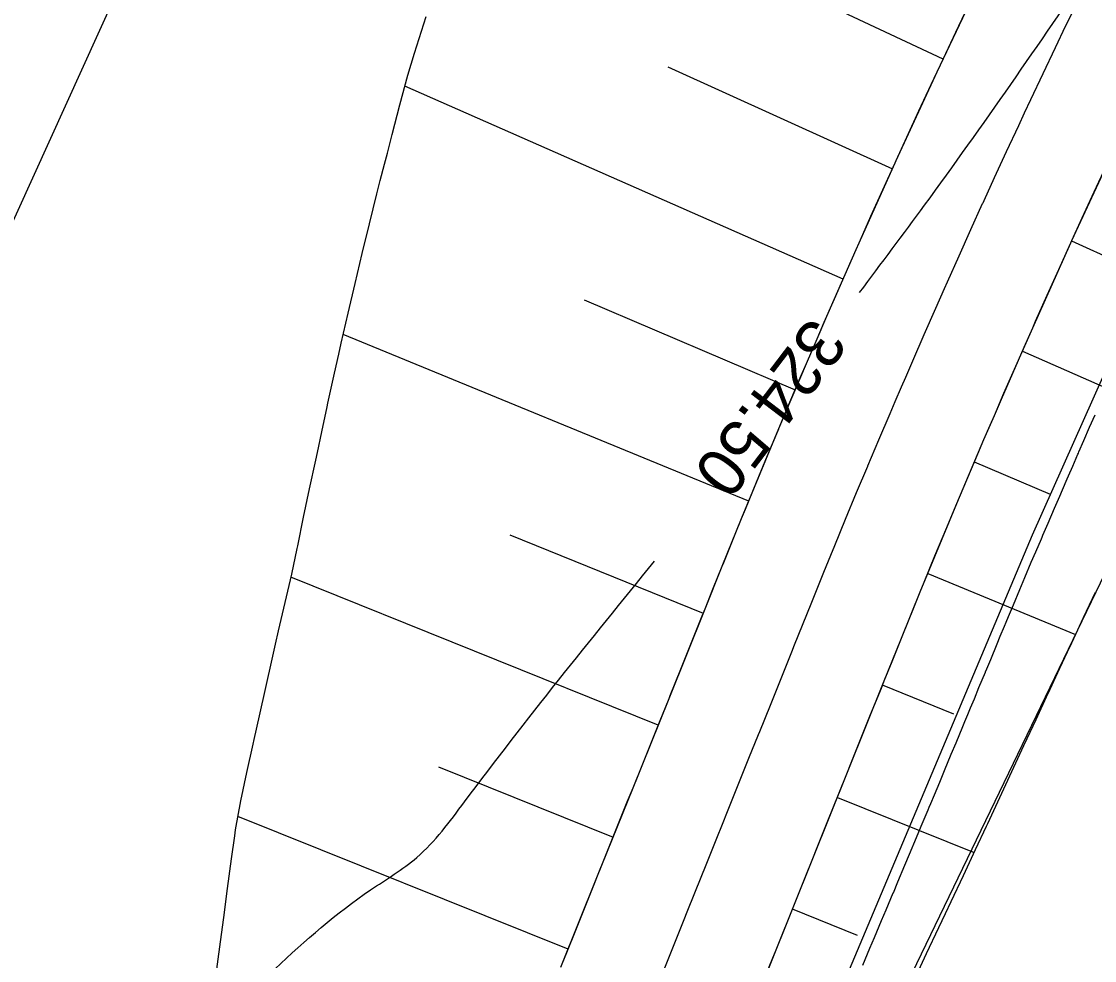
# Model space of a CAD drawing. Extents: x -564037 to -563827, y -1163561 to -1163412.
# Drawn here: x -563980.78 to -563969.67, y -1163490.36 to -1163480.64 of the extents above; entities that cross this region are included whole.
import ezdxf

# ---------------------------------------------------------------- set-up
doc = ezdxf.new("R2010")
doc.units = 0
for name, color, linetype in [('Default', 7, 'Continuous'), ('Definiční bod kú', 7, 'Continuous'), ('Line', 7, 'Continuous'), ('Vrstva 24', 7, 'Continuous'), ('Vrstva 25', 7, 'Continuous'), ('Vrstva 26', 7, 'Continuous')]:
    doc.layers.add(name, color=color, linetype=linetype)

msp = doc.modelspace()

# ---------------------------------------------------------------- linework, layer by layer
msp.add_lwpolyline([(-563976.663, -1163501.462), (-563964.742, -1163493.091), (-563961.829, -1163491.15), (-563957.41, -1163486.988), (-563956.735, -1163486.627), (-563953.281, -1163481.221), (-563953.993, -1163478.343), (-563957.796, -1163470.824), (-563957.81, -1163470.439), (-563957.835, -1163469.754), (-563958.239, -1163469.063), (-563958.187, -1163468.683), (-563959.529, -1163466.077), (-563960.166, -1163464.984), (-563964.31, -1163473.527), (-563966.903, -1163478.544), (-563968.406, -1163481.669), (-563970.316, -1163485.955), (-563973.278, -1163492.988), (-563976.735, -1163500.155), (-563977.161, -1163500.889), (-563977.363, -1163501.307)], close=True)
for points in [[(-563960.591, -1163493.664), (-563961.319, -1163493.948), (-563961.866, -1163494.161), (-563963.182, -1163494.674), (-563968.138, -1163497.33), (-563968.634, -1163497.596), (-563970.944, -1163498.688), (-563971.597, -1163498.997), (-563976.56, -1163501.343), (-563977.332, -1163501.295), (-563976.988, -1163500.693), (-563975.559, -1163498.192), (-563975.396, -1163497.906), (-563973.296, -1163494.084), (-563973.133, -1163493.747), (-563971.654, -1163490.682), (-563969.513, -1163486.248), (-563968.702, -1163484.611), (-563968.142, -1163483.478), (-563966.349, -1163479.855)], [(-563975.198, -1163490.428), (-563974.825, -1163489.5), (-563974.451, -1163488.572), (-563974.078, -1163487.645), (-563973.705, -1163486.717), (-563973.527, -1163486.276), (-563973.328, -1163485.785), (-563972.941, -1163484.852), (-563972.655, -1163484.178), (-563972.545, -1163483.923), (-563972.444, -1163483.689), (-563972.14, -1163482.998), (-563971.736, -1163482.1), (-563971.725, -1163482.077), (-563971.302, -1163481.16), (-563970.869, -1163480.247)], [(-563973.343, -1163491.175), (-563972.969, -1163490.247), (-563972.596, -1163489.319), (-563972.223, -1163488.391), (-563971.849, -1163487.464), (-563971.672, -1163487.023), (-563971.476, -1163486.542), (-563971.097, -1163485.627), (-563970.817, -1163484.966), (-563970.709, -1163484.716), (-563970.61, -1163484.487), (-563970.312, -1163483.809), (-563969.916, -1163482.93), (-563969.906, -1163482.907), (-563969.49, -1163482.008), (-563969.066, -1163481.113), (-563968.97, -1163480.914), (-563968.633, -1163480.223)], [(-563975.175, -1163490.37), (-563975.064, -1163490.095), (-563974.953, -1163489.819), (-563974.842, -1163489.544), (-563974.825, -1163489.5), (-563974.732, -1163489.269), (-563974.621, -1163488.994), (-563974.51, -1163488.718), (-563974.451, -1163488.572), (-563974.399, -1163488.443), (-563974.288, -1163488.168), (-563974.177, -1163487.892), (-563974.078, -1163487.645), (-563974.067, -1163487.617), (-563973.956, -1163487.342), (-563973.845, -1163487.066), (-563973.734, -1163486.791), (-563973.705, -1163486.717), (-563973.623, -1163486.516), (-563973.527, -1163486.276), (-563973.512, -1163486.24), (-563973.4, -1163485.962), (-563973.328, -1163485.785), (-563973.287, -1163485.685), (-563973.173, -1163485.407), (-563973.058, -1163485.13), (-563972.942, -1163484.854), (-563972.941, -1163484.852), (-563972.826, -1163484.578), (-563972.708, -1163484.302), (-563972.655, -1163484.178), (-563972.59, -1163484.027), (-563972.545, -1163483.923), (-563972.471, -1163483.751), (-563972.351, -1163483.477), (-563972.23, -1163483.202), (-563972.14, -1163482.998), (-563972.109, -1163482.928), (-563971.987, -1163482.654), (-563971.864, -1163482.381), (-563971.74, -1163482.108), (-563971.736, -1163482.1), (-563971.725, -1163482.077), (-563971.615, -1163481.836), (-563971.49, -1163481.563), (-563971.363, -1163481.292), (-563971.302, -1163481.16), (-563971.236, -1163481.02), (-563971.108, -1163480.749), (-563970.98, -1163480.478)], [(-563974.136, -1163490.468), (-563974.025, -1163490.193), (-563973.915, -1163489.918), (-563973.897, -1163489.873), (-563973.804, -1163489.642), (-563973.693, -1163489.367), (-563973.582, -1163489.092), (-563973.524, -1163488.946), (-563973.471, -1163488.816), (-563973.361, -1163488.541), (-563973.25, -1163488.266), (-563973.15, -1163488.018), (-563973.139, -1163487.99), (-563973.028, -1163487.715), (-563972.917, -1163487.44), (-563972.807, -1163487.164), (-563972.777, -1163487.09), (-563972.696, -1163486.889), (-563972.599, -1163486.649), (-563972.585, -1163486.614), (-563972.474, -1163486.339), (-563972.402, -1163486.163), (-563972.361, -1163486.064), (-563972.249, -1163485.789), (-563972.135, -1163485.515), (-563972.02, -1163485.241), (-563972.019, -1163485.239), (-563971.905, -1163484.968), (-563971.789, -1163484.695), (-563971.736, -1163484.572), (-563971.672, -1163484.422), (-563971.627, -1163484.32), (-563971.554, -1163484.15), (-563971.435, -1163483.878), (-563971.316, -1163483.606), (-563971.226, -1163483.404), (-563971.195, -1163483.335), (-563971.074, -1163483.064), (-563970.952, -1163482.793), (-563970.83, -1163482.523), (-563970.826, -1163482.515), (-563970.816, -1163482.492), (-563970.706, -1163482.253), (-563970.582, -1163481.983), (-563970.457, -1163481.714), (-563970.396, -1163481.584), (-563970.331, -1163481.446), (-563970.205, -1163481.177), (-563970.077, -1163480.909), (-563969.968, -1163480.68), (-563969.949, -1163480.641), (-563969.87, -1163480.479)], [(-563978.77, -1163490.523), (-563978.73, -1163490.219), (-563978.713, -1163490.091), (-563978.69, -1163489.915), (-563978.649, -1163489.612), (-563978.608, -1163489.308), (-563978.575, -1163489.069), (-563978.566, -1163489.005), (-563978.513, -1163488.707), (-563978.449, -1163488.413), (-563978.384, -1163488.119), (-563978.374, -1163488.072), (-563978.319, -1163487.825), (-563978.253, -1163487.532), (-563978.187, -1163487.238), (-563978.152, -1163487.083), (-563978.121, -1163486.945), (-563978.054, -1163486.652), (-563977.986, -1163486.359), (-563977.93, -1163486.095), (-563977.923, -1163486.065), (-563977.862, -1163485.77), (-563977.8, -1163485.475), (-563977.737, -1163485.18), (-563977.72, -1163485.101), (-563977.674, -1163484.885), (-563977.619, -1163484.629), (-563977.611, -1163484.589), (-563977.542, -1163484.279), (-563977.498, -1163484.081), (-563977.473, -1163483.969), (-563977.402, -1163483.659), (-563977.329, -1163483.35), (-563977.256, -1163483.041), (-563977.255, -1163483.039), (-563977.18, -1163482.732), (-563977.103, -1163482.424), (-563977.068, -1163482.285), (-563977.025, -1163482.116), (-563976.995, -1163482), (-563976.946, -1163481.808), (-563976.865, -1163481.5), (-563976.782, -1163481.193), (-563976.715, -1163480.966), (-563976.691, -1163480.89), (-563976.594, -1163480.588)], [(-563978.77, -1163490.523), (-563978.73, -1163490.219), (-563978.713, -1163490.091), (-563978.69, -1163489.915), (-563978.649, -1163489.612), (-563978.608, -1163489.308), (-563978.575, -1163489.069), (-563978.566, -1163489.005), (-563978.513, -1163488.707), (-563978.449, -1163488.413), (-563978.384, -1163488.119), (-563978.374, -1163488.072), (-563978.319, -1163487.825), (-563978.253, -1163487.532), (-563978.187, -1163487.238), (-563978.152, -1163487.083), (-563978.121, -1163486.945), (-563978.054, -1163486.652), (-563977.986, -1163486.359), (-563977.93, -1163486.095), (-563977.923, -1163486.065), (-563977.862, -1163485.77), (-563977.8, -1163485.475), (-563977.737, -1163485.18), (-563977.72, -1163485.101), (-563977.674, -1163484.885), (-563977.619, -1163484.629), (-563977.611, -1163484.589), (-563977.542, -1163484.279), (-563977.498, -1163484.081), (-563977.473, -1163483.969), (-563977.402, -1163483.659), (-563977.329, -1163483.35), (-563977.256, -1163483.041), (-563977.255, -1163483.039), (-563977.18, -1163482.732), (-563977.103, -1163482.424), (-563977.068, -1163482.285), (-563977.025, -1163482.116), (-563976.995, -1163482), (-563976.946, -1163481.808), (-563976.865, -1163481.5), (-563976.782, -1163481.193), (-563976.715, -1163480.966), (-563976.691, -1163480.89), (-563976.594, -1163480.588)], [(-563973.098, -1163490.566), (-563972.987, -1163490.291), (-563972.969, -1163490.247), (-563972.876, -1163490.016), (-563972.765, -1163489.74), (-563972.655, -1163489.465), (-563972.596, -1163489.319), (-563972.544, -1163489.19), (-563972.433, -1163488.914), (-563972.322, -1163488.639), (-563972.223, -1163488.391), (-563972.211, -1163488.364), (-563972.101, -1163488.088), (-563971.99, -1163487.813), (-563971.879, -1163487.538), (-563971.849, -1163487.464), (-563971.768, -1163487.262), (-563971.672, -1163487.023), (-563971.657, -1163486.987), (-563971.547, -1163486.715), (-563971.476, -1163486.542), (-563971.436, -1163486.443), (-563971.324, -1163486.171), (-563971.212, -1163485.9), (-563971.098, -1163485.629), (-563971.097, -1163485.627), (-563970.984, -1163485.358), (-563970.869, -1163485.088), (-563970.817, -1163484.966), (-563970.753, -1163484.818), (-563970.709, -1163484.716), (-563970.636, -1163484.548), (-563970.519, -1163484.279), (-563970.401, -1163484.01), (-563970.312, -1163483.809), (-563970.282, -1163483.741), (-563970.162, -1163483.473), (-563970.041, -1163483.205), (-563969.92, -1163482.937), (-563969.916, -1163482.93), (-563969.906, -1163482.907), (-563969.798, -1163482.67), (-563969.675, -1163482.403), (-563969.551, -1163482.137)], [(-563971.537, -1163490.555), (-563971.41, -1163490.286), (-563971.283, -1163490.017), (-563971.216, -1163489.874), (-563971.157, -1163489.748), (-563971.03, -1163489.479), (-563970.904, -1163489.21), (-563970.791, -1163488.968), (-563970.778, -1163488.94), (-563970.653, -1163488.671), (-563970.527, -1163488.402), (-563970.402, -1163488.132), (-563970.368, -1163488.06), (-563970.277, -1163487.863), (-563970.168, -1163487.628), (-563970.152, -1163487.594), (-563970.03, -1163487.332), (-563969.952, -1163487.164), (-563969.908, -1163487.069), (-563969.785, -1163486.808), (-563969.662, -1163486.546)], [(-563971.537, -1163490.555), (-563971.41, -1163490.286), (-563971.283, -1163490.017), (-563971.216, -1163489.874), (-563971.157, -1163489.748), (-563971.03, -1163489.479), (-563970.904, -1163489.21), (-563970.791, -1163488.968), (-563970.778, -1163488.94), (-563970.653, -1163488.671), (-563970.527, -1163488.402), (-563970.402, -1163488.132), (-563970.368, -1163488.06), (-563970.277, -1163487.863), (-563970.168, -1163487.628), (-563970.152, -1163487.594), (-563970.03, -1163487.332), (-563969.952, -1163487.164), (-563969.908, -1163487.069), (-563969.785, -1163486.808), (-563969.662, -1163486.546)]]:
    msp.add_lwpolyline(points)
at = {"layer": 'Default'}
msp.add_lwpolyline([(-563972.072, -1163490.408), (-563971.998, -1163490.232), (-563971.95, -1163490.12), (-563971.877, -1163489.946), (-563971.829, -1163489.833), (-563971.756, -1163489.659), (-563971.756, -1163489.659), (-563971.755, -1163489.658), (-563971.707, -1163489.544), (-563971.635, -1163489.372), (-563971.587, -1163489.257), (-563971.515, -1163489.086), (-563971.466, -1163488.969), (-563971.395, -1163488.799), (-563971.384, -1163488.773), (-563971.368, -1163488.735), (-563971.33, -1163488.644), (-563971.275, -1163488.512), (-563971.225, -1163488.393), (-563971.155, -1163488.224), (-563971.105, -1163488.105), (-563971.036, -1163487.937), (-563971.014, -1163487.885), (-563970.984, -1163487.812), (-563970.955, -1163487.744), (-563970.916, -1163487.65), (-563970.868, -1163487.533), (-563970.802, -1163487.373), (-563970.8, -1163487.368), (-563970.797, -1163487.363), (-563970.747, -1163487.242), (-563970.68, -1163487.081), (-563970.647, -1163487.002), (-563970.604, -1163486.898), (-563970.586, -1163486.855), (-563970.563, -1163486.799), (-563970.511, -1163486.677), (-563970.445, -1163486.518), (-563970.392, -1163486.395), (-563970.326, -1163486.237), (-563970.28, -1163486.13), (-563970.222, -1163485.995), (-563970.215, -1163485.978), (-563970.206, -1163485.957), (-563970.153, -1163485.832), (-563970.086, -1163485.676), (-563970.032, -1163485.551), (-563969.965, -1163485.396), (-563969.955, -1163485.372), (-563969.942, -1163485.342), (-563969.897, -1163485.24), (-563969.844, -1163485.116), (-563969.839, -1163485.106), (-563969.834, -1163485.094), (-563969.783, -1163484.977), (-563969.722, -1163484.837), (-563969.666, -1163484.709)], dxfattribs=at)
at = {"layer": 'Definiční bod kú'}
msp.add_lwpolyline([(-564036.505, -1163529.976), (-564035.88, -1163528.59), (-564032.62, -1163523.46), (-564027.5, -1163518.53), (-564023.88, -1163515.79), (-564019.18, -1163512.89), (-564014.48, -1163510.5), (-564004.65, -1163507.04), (-563996.46, -1163502.51), (-563993.72, -1163500.97), (-563990.58, -1163498.69), (-563987.18, -1163495.32), (-563983.19, -1163487.81), (-563979.82, -1163480.39), (-563975.55, -1163472.37), (-563971.76, -1163466.68), (-563970.57, -1163458.32), (-563969.42, -1163449.87), (-563967.93, -1163441.99), (-563966.12, -1163434.66), (-563963.95, -1163427.04), (-563963.19, -1163422.98), (-563961.48, -1163418.93), (-563957.126, -1163412.494)], dxfattribs=at)
at = {"layer": 'Line'}
for p, q in [((-563971.24, -1163481.029), (-563975.992, -1163478.796)), ((-563974.092, -1163481.106), (-563971.765, -1163482.164)), ((-563972.275, -1163483.305), (-563976.813, -1163481.308)), ((-563969.08, -1163483.289), (-563969.908, -1163482.911)), ((-563974.958, -1163483.521), (-563972.771, -1163484.452)), ((-563973.253, -1163485.605), (-563977.452, -1163483.877)), ((-563970.418, -1163484.052), (-563968.806, -1163484.762)), ((-563970.128, -1163485.534), (-563970.916, -1163485.199)), ((-563975.726, -1163485.954), (-563973.723, -1163486.764)), ((-563974.19, -1163487.923), (-563977.994, -1163486.392)), ((-563971.398, -1163486.352), (-563969.867, -1163486.983)), ((-563971.129, -1163487.809), (-563971.868, -1163487.51)), ((-563976.466, -1163488.355), (-563974.657, -1163489.083)), ((-563972.335, -1163488.67), (-563970.918, -1163489.24)), ((-563975.123, -1163490.242), (-563978.542, -1163488.867)), ((-563972.126, -1163490.101), (-563972.801, -1163489.829))]:
    msp.add_line(p, q, dxfattribs=at)
at = {"layer": 'Vrstva 24'}
for points in [[(-563987.107, -1163486.915), (-563987.454, -1163489.613), (-563987.517, -1163490.15), (-563987.54, -1163490.422), (-563987.53, -1163490.559), (-563987.493, -1163490.695), (-563987.417, -1163490.784), (-563987.298, -1163490.832), (-563987.065, -1163490.801), (-563986.897, -1163490.636), (-563986.866, -1163490.616), (-563986.653, -1163490.561), (-563986.65, -1163490.24), (-563986.645, -1163490.2), (-563986.382, -1163489.381), (-563986.092, -1163488.576), (-563985.799, -1163487.775), (-563985.528, -1163486.967), (-563985.38, -1163486.476), (-563984.961, -1163484.997), (-563984.678, -1163484.011), (-563984.372, -1163483.032), (-563984.225, -1163482.649), (-563983.962, -1163482.075), (-563983.672, -1163481.512), (-563983.189, -1163480.348), (-563983.119, -1163479.959), (-563982.881, -1163478.598), (-563982.738, -1163477.921), (-563982.65, -1163477.583), (-563982.6, -1163477.415), (-563982.546, -1163477.247), (-563982.332, -1163477.109), (-563982.215, -1163477.074), (-563982.092, -1163477.059), (-563981.971, -1163477.035), (-563981.858, -1163476.974), (-563981.222, -1163476.317), (-563980.763, -1163475.576), (-563980.303, -1163473.933), (-563980.283, -1163473.505), (-563980.299, -1163473.076), (-563980.318, -1163472.648), (-563980.308, -1163472.221), (-563980.208, -1163471.241), (-563979.978, -1163470.27), (-563979.506, -1163469.655), (-563979.053, -1163469.383), (-563978.331, -1163469.068), (-563977.756, -1163469.029), (-563977.053, -1163469.053), (-563976.495, -1163468.977), (-563976.227, -1163468.861), (-563976.095, -1163468.775), (-563975.963, -1163468.666), (-563975.645, -1163468.239), (-563975.569, -1163468.015), (-563975.54, -1163467.788), (-563975.712, -1163467.263), (-563975.92, -1163467.014), (-563976.134, -1163466.799), (-563976.603, -1163466.431), (-563977.767, -1163465.694), (-563978.114, -1163465.416), (-563978.319, -1163465.046), (-563978.354, -1163464.593), (-563978.366, -1163464.139), (-563978.374, -1163463.685), (-563978.396, -1163463.232), (-563978.403, -1163463.165), (-563978.508, -1163462.771), (-563978.665, -1163462.394), (-563979.088, -1163461.691), (-563979.473, -1163461.171), (-563980.119, -1163460.346)], [(-563978.297, -1163509.021), (-563978.261, -1163509.003), (-563973.613, -1163506.565), (-563973.263, -1163506.351), (-563972.852, -1163506.074), (-563964.784, -1163500.778), (-563963.064, -1163499.262), (-563960.133, -1163495.845), (-563958.857, -1163494.133), (-563956.661, -1163490.461), (-563954.703, -1163486.917), (-563951.017, -1163480.396), (-563950.659, -1163479.782), (-563950.563, -1163479.619)]]:
    msp.add_spline(points, degree=3, dxfattribs=at)
at = {"layer": 'Vrstva 25'}
msp.add_spline([(-563979.181, -1163499.008), (-563978.428, -1163498.506), (-563977.533, -1163497.79), (-563971.745, -1163492.882), (-563969.933, -1163491.157), (-563968.824, -1163489.747), (-563966.163, -1163485.494), (-563965.399, -1163484.181), (-563964.1, -1163481.868), (-563961.431, -1163477.021), (-563960.731, -1163475.725), (-563960.044, -1163474.189), (-563959.617, -1163472.641), (-563959.116, -1163469.866), (-563959.228, -1163469.046), (-563959.512, -1163468.326), (-563959.82, -1163467.638), (-563960.515, -1163466.313), (-563961.208, -1163465.1)], degree=3, dxfattribs=at)
at = {"layer": 'Vrstva 26'}
for points in [[(-563972.104, -1163483.444), (-563971.432, -1163482.54), (-563969.672, -1163480.022), (-563968.003, -1163477.443), (-563966.946, -1163475.644), (-563966.582, -1163474.952), (-563966.094, -1163473.851), (-563965.88, -1163473.286), (-563965.678, -1163472.709), (-563965.489, -1163472.088), (-563965.344, -1163471.461), (-563965.237, -1163470.83), (-563965.169, -1163470.196), (-563965.25, -1163468.999), (-563965.418, -1163468.435), (-563965.618, -1163467.888), (-563966.136, -1163466.849), (-563967.179, -1163465.223), (-563969.294, -1163462.205), (-563970.81, -1163460.003), (-563971.343, -1163459.213), (-563971.719, -1163458.626), (-563972.18, -1163457.904), (-563973.29, -1163456.114), (-563973.826, -1163455.207), (-563974.35, -1163454.292), (-563975.821, -1163451.273), (-563976.512, -1163449.594), (-563977.063, -1163448.162), (-563977.464, -1163447.121)], [(-563980.746, -1163506.255), (-563980.047, -1163505.928), (-563978.898, -1163505.186), (-563978.091, -1163504.559), (-563977.304, -1163503.908), (-563976.514, -1163503.264), (-563975.695, -1163502.656), (-563974.591, -1163501.929), (-563973.468, -1163501.232), (-563972.341, -1163500.538), (-563971.226, -1163499.825), (-563970.447, -1163499.268), (-563969.15, -1163497.951), (-563964.517, -1163492.611), (-563963.2, -1163490.7), (-563960.284, -1163485.41), (-563958.779, -1163482.786), (-563956.142, -1163478.307), (-563954.428, -1163475.228)], [(-563991.611, -1163485.501), (-563991.561, -1163485.341), (-563991.21, -1163484.328), (-563991.006, -1163483.823), (-563990.782, -1163483.317), (-563990.669, -1163483.212), (-563989.835, -1163483.385), (-563989.335, -1163483.591), (-563988.852, -1163483.806), (-563988.416, -1163484.095), (-563988.226, -1163484.288), (-563988.06, -1163484.524), (-563987.844, -1163485.266), (-563987.9, -1163486.009), (-563988.137, -1163487.627), (-563988.511, -1163490.277), (-563988.935, -1163493.479), (-563989.128, -1163493.944), (-563989.201, -1163494.071), (-563989.25, -1163494.355), (-563988.964, -1163494.223), (-563988.759, -1163494.176), (-563988.506, -1163494.004), (-563988.295, -1163493.783), (-563987.947, -1163493.254), (-563987.614, -1163492.703), (-563987.194, -1163492.246), (-563986.965, -1163492.108), (-563986.555, -1163492.017), (-563986.094, -1163492.011), (-563985.68, -1163491.951), (-563985.522, -1163491.857), (-563985.413, -1163491.697), (-563985.286, -1163491.116), (-563985.31, -1163490.532), (-563985.383, -1163489.947), (-563985.403, -1163489.364), (-563985.38, -1163489.09), (-563984.85, -1163487.266), (-563984.13, -1163485.089), (-563983.855, -1163484.492), (-563982.893, -1163482.465), (-563982.427, -1163481.437), (-563982.206, -1163480.907), (-563982.1, -1163480.637), (-563981.997, -1163480.363), (-563981.967, -1163480.031), (-563981.995, -1163479.694), (-563982.002, -1163479.122), (-563981.99, -1163478.836), (-563981.972, -1163478.693), (-563981.942, -1163478.551), (-563981.849, -1163478.489), (-563981.662, -1163478.435), (-563981.467, -1163478.411), (-563981.273, -1163478.37), (-563981.089, -1163478.263), (-563980.515, -1163477.708), (-563980.017, -1163477.13), (-563979.334, -1163476.087)], [(-564001.195, -1163498.271), (-563999.625, -1163497.54), (-563999.32, -1163497.49), (-563999.014, -1163497.455), (-563998.404, -1163497.374), (-563997.456, -1163497.19), (-563996.983, -1163497.106), (-563996.746, -1163497.08), (-563996.628, -1163497.073), (-563996.51, -1163497.07), (-563996.001, -1163497.405), (-563995.843, -1163497.69), (-563995.811, -1163497.929), (-563995.865, -1163498.008), (-563995.966, -1163498.084), (-563996.177, -1163498.245), (-563996.314, -1163498.396), (-563996.473, -1163498.559), (-563996.786, -1163498.911), (-563996.954, -1163499.618), (-563996.725, -1163499.926), (-563996.435, -1163500.208), (-563996.113, -1163500.428), (-563995.791, -1163500.55), (-563995.579, -1163500.527), (-563995.362, -1163500.405), (-563995.147, -1163500.225), (-563994.94, -1163500.032), (-563994.454, -1163499.316), (-563994.189, -1163498.497), (-563993.911, -1163497.703), (-563993.694, -1163497.356), (-563993.385, -1163497.063), (-563993.106, -1163496.925), (-563992.801, -1163496.863), (-563992.211, -1163496.877), (-563991.901, -1163497.039), (-563991.591, -1163497.33), (-563991.287, -1163497.564), (-563990.995, -1163497.556), (-563990.269, -1163497.037), (-563989.554, -1163496.504), (-563988.84, -1163495.969), (-563988.119, -1163495.444), (-563987.86, -1163495.24), (-563987.725, -1163495.146), (-563987.573, -1163495.071), (-563987.369, -1163495.063), (-563987.165, -1163495.092), (-563986.561, -1163495.087), (-563985.951, -1163495.108), (-563984.727, -1163495.135), (-563983.531, -1163494.982), (-563982.954, -1163494.778), (-563982.673, -1163494.634), (-563982.398, -1163494.458), (-563981.989, -1163494.127), (-563981.638, -1163493.78), (-563980.962, -1163493.086), (-563979.072, -1163491.35), (-563977.168, -1163489.628), (-563976.69, -1163489.292), (-563976.196, -1163488.717), (-563974.229, -1163486.225)], [(-563979.339, -1163513.451), (-563976.454, -1163512.115), (-563974.079, -1163510.944), (-563968.189, -1163507.943), (-563964.488, -1163505.88), (-563958.479, -1163502.145), (-563957, -1163500.857), (-563954.437, -1163497.718), (-563953.277, -1163496.363), (-563952.789, -1163495.73), (-563951.998, -1163494.583), (-563951.243, -1163493.409), (-563950.48, -1163492.242), (-563949.665, -1163491.113), (-563947.525, -1163488.408), (-563947.448, -1163488.312)]]:
    msp.add_spline(points, degree=3, dxfattribs=at)

# ---------------------------------------------------------------- texts
at = {"layer": 'Vrstva 25'}
msp.add_text('324.50', height=0.5, rotation=232.6996, dxfattribs=at).set_placement((-563972.605, -1163483.676))

doc.saveas('drawing.dxf')
